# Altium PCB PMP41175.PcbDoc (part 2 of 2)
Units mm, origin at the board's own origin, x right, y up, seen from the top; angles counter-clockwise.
Board outline 50 x 29 mm, 6 copper layers (Top Layer, Signal Layer 1, Signal Layer 2, Signal Layer 3, Signal Layer 4, Bottom Layer), stack 1.56 mm thick; 56 components, 26 nets, 110 pads, 28 vias.
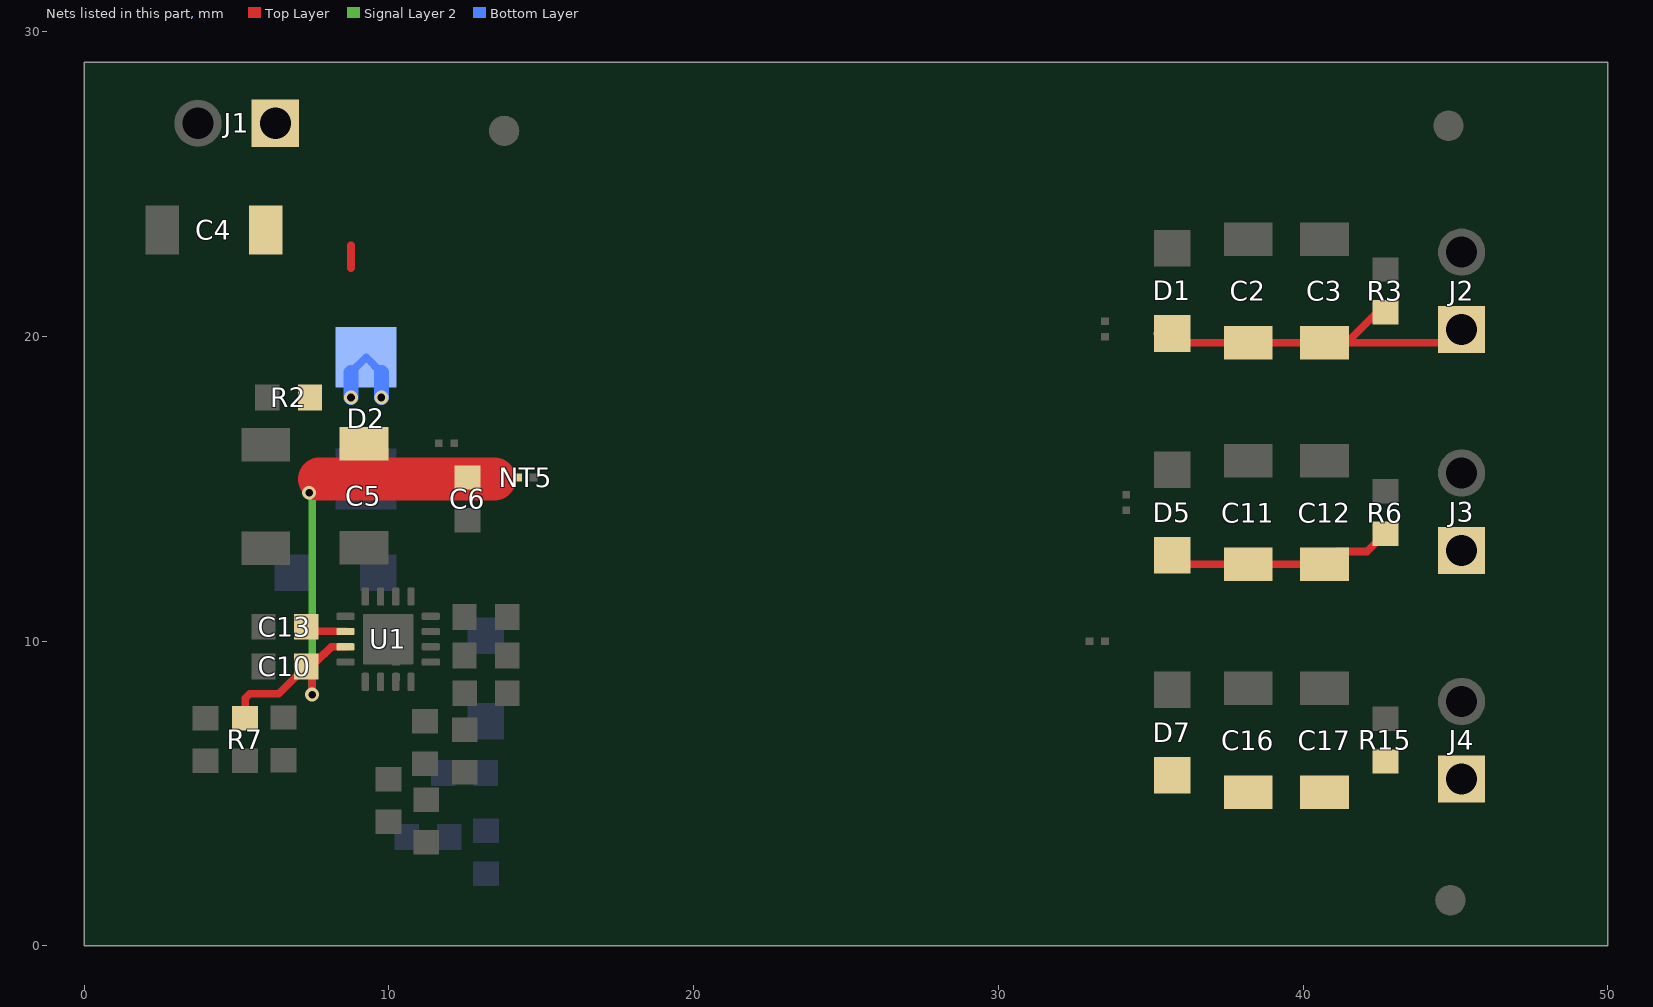
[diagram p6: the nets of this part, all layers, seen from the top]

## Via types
v1: diameter 0.457, hole 0.254, Top Layer to Bottom Layer, 15 vias
v2: diameter 0.4, hole 0.2, Top Layer to Bottom Layer, 8 vias
v3: diameter 0.5, hole 0.2, Top Layer to Bottom Layer, 5 vias

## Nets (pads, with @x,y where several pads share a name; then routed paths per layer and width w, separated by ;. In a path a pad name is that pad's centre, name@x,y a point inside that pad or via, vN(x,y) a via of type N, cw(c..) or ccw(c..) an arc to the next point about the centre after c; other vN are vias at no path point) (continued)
VBIAS: C4.1 C5.1 C6.1 C10.1 D2.2 J1.1 NT5.2 R2.2 R7.1 U1.3 | length 23.3
  Top Layer w0.254: R7.1@5.304,7.473 R7.1@5.279,7.473 5.279,8.124 5.428,8.273 6.379,8.273 C10.1@7.279,9.173 7.479,8.973 v1(7.479,8.244) ; C10.1@7.479,9.173 7.479,9.198 7.879,9.598 7.896,9.598 8.114,9.816 U1.3@8.572,9.816 ; 8.75,22.25 8.75,23 ; C6.1@12.579,15.373 NT5.2@14.175,15.373
  Top Layer w1.4: 7.706,15.323 13.462,15.323
  Signal Layer 2 w0.254: v1(7.379,14.873) 7.379,14.818 7.479,14.718 v1(7.479,8.244)
  Bottom Layer w0.254: D2.2@8.75,18.82 D2.2@9.25,19.32 D2.2@9.75,18.82
  Bottom Layer w0.5: v1(8.75,18) D2.2@8.75,18.82 ; v1(9.75,18) D2.2@9.75,18.82
VCC: C13.1 U1.2 | length 1.1
  Top Layer w0.254: C13.1@7.479,10.373 C13.1@7.529,10.423 ; C13.1@7.529,10.323 U1.2@8.579,10.323
VOUT1: C2.1 C3.1 D1.1 J2.1 R3.2 | length 12.3
  Top Layer w0.254: D1.1@35.206,20.1 35.506,19.8 C3.1@41.431,19.8 ; R3.2@42.456,20.8 42.431,20.8 C3.1@41.431,19.8 ; J2.1@45.206,20.23 44.776,19.8 C3.1@41.431,19.8
  Bottom Layer w0.254: J2.1@44.839,19.863 J2.1@45.206,20.23
VOUT2: C11.1 C12.1 D5.1 J3.1 R6.2 | length 8.1
  Top Layer w0.254: D5.1@35.706,12.824 36.006,12.524 C11.1@38.206,12.524 C12.1@40.706,12.524 41.129,12.947 42.104,12.947 42.681,13.524 R6.2@42.706,13.524
  Bottom Layer w0.254: J3.1@44.839,12.612 J3.1@45.206,12.98
VOUT3: C16.1 C17.1 D7.1 J4.1 R15.2 | length 0.5
  Bottom Layer w0.254: J4.1@44.839,5.112 J4.1@45.206,5.48
pads on no net: FID1.1 FID2.1 FID3.1 U1.4 U1.12 U1.15

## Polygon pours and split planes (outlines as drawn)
VBIAS on Top Layer "TOP_LAYER_VBIAS_P042" (solid, pour order 42): 10.5,22.5 10.5,15.291 6.956,15.291 6.956,19.544 6.956,22.5
GND3 on Top Layer "TOP_LAYER_GND3_P060" (solid, pour order 60): 47.956,7.5 47.206,6.75 34.206,6.75 33.456,7.5 33.456,10.156 33.8,10.5 47.206,10.5 47.956,9.75
GND2 on Top Layer "TOP_LAYER_GND2_P055" (solid, pour order 55): 47.956,15 47.206,14.25 34.206,14.25 33.456,15 33.456,17 34.207,17.751 47.205,17.751 47.956,17
GND1 on Top Layer "TOP_LAYER_GND1_P053" (solid, pour order 53): 47.956,22.25 47.206,21.5 33.956,21.5 33.206,22.25 33.206,24.25 33.956,25 47.206,25 47.956,24.25
PGND on Top Layer "TOP_LAYER_PGND_P044" (solid, pour order 44): 14.706,22.498 10.75,22.498 10.75,16.886 10.886,16.75 12.25,16.75 14.706,19.206
PGND on Top Layer "TOP_LAYER_PGND_P043" (solid, pour order 43): 0.5,28.284 3.216,28.284 4.25,27.25 4.25,20.75 4.586,20.414 6.196,20.414 13.206,13.405 13.206,5.957 14.648,5.957 14.826,5.779 14.826,3.442 14.956,3.312 14.956,0.496 0.5,0.496
SW on Top Layer "TOP_LAYER_SW_P040" (solid, pour order 40): 10.081,11.975 11.288,13.182 12.181,13.182 12.158,12.352 10.979,11.173 10.081,11.173
VBIAS on Top Layer "TOP_LAYER_VBIAS_P041" (solid, pour order 41): 10.5,22.75 10.75,23 10.75,25.5 7.865,28.385 5.5,28.385 5.5,22.75
AGND on Top Layer "TOP_LAYER_AGND_P039" (solid, remove dead copper, pour order 39): 14.956,2.884 14.956,11.273 13.379,11.273 13.379,4.173 11.484,4.173 10.484,5.173 10.539,5.228 10.539,8.673 9.764,8.673 9.456,8.365 9.456,7.645 6.959,5.148 5.784,5.148 5.784,3.973 6.873,2.884
GND1 on Bottom Layer "BOTTOM_LAYER_GND1_P059" (solid, pour order 59): 33.956,18.75 33.206,19.5 33.206,24.25 33.956,25 47.206,25 47.956,24.25 47.956,19.5 47.206,18.75
GND3 on Bottom Layer "BOTTOM_LAYER_GND3_P057" (solid, pour order 57): 34.206,4 33.456,4.75 33.456,9.75 34.206,10.5 47.206,10.5 47.956,9.75 47.956,4.75 47.206,4
GND2 on Bottom Layer "BOTTOM_LAYER_GND2_P054" (solid, pour order 54): 34.206,11.5 33.456,12.25 33.456,17 34.206,17.75 47.206,17.75 47.956,17 47.956,12.25 47.206,11.5
PGND on Bottom Layer "BOTTOM_LAYER_PGND_P052" (solid, pour order 52): 9.619,20.181 10.206,20.768 10.206,22.51 14.713,22.51 14.713,18.507 14.713,11.345 14.953,11.106 14.953,3.417 14.953,0.496 -2.04,0.496 -2.294,0.75 -2.294,19.292 -1.405,20.181
GND1 on Signal Layer 1 "SIGNAL_LAYER_1_GND1_P058" (solid, pour order 58): 33.956,18.75 33.206,19.5 33.206,24.25 33.956,25 47.206,25 47.956,24.25 47.956,19.5 47.206,18.75
GND3 on Signal Layer 1 "SIGNAL_LAYER_1_GND3_P056" (solid, pour order 56): 34.206,4 33.456,4.75 33.456,9.75 34.206,10.5 47.206,10.5 47.956,9.75 47.956,4.75 47.206,4
GND2 on Signal Layer 1 "SIGNAL_LAYER_1_GND2_P049" (solid, pour order 49): 34.206,11.5 33.456,12.25 33.456,17 34.206,17.75 47.206,17.75 47.956,17 47.956,12.25 47.206,11.5
PGND on Signal Layer 1 "SIGNAL_LAYER_1_PGND_P045" (solid, pour order 45): 10.206,22.5 14.706,22.5 14.706,18.5 14.25,18.044 14.25,11.816 14.953,11.113 14.953,3.417 14.953,0.496 -2.04,0.496 -2.294,0.75 -2.294,19.292 -1.405,20.181 9.637,20.181 10.206,20.75
PGND on Signal Layer 2 "SIGNAL_LAYER_2_PGND_P046" (solid, pour order 46): 9.637,20.181 10.206,20.75 10.206,22.5 14.706,22.5 14.706,18.5 13.479,17.273 13.479,12.444 14.956,10.968 14.956,0.496 -2.04,0.496 -2.294,0.75 -2.294,19.292 -1.405,20.181
PGND on Signal Layer 3 "SIGNAL_LAYER_3_PGND_P050" (solid, pour order 50): 9.637,20.181 10.206,20.75 10.206,22.5 14.706,22.5 14.706,18.5 13.479,17.273 13.479,9.005 14.953,7.532 14.953,3.417 14.953,0.496 -2.04,0.496 -2.294,0.75 -2.294,19.292 -1.405,20.181
PGND on Signal Layer 4 "SIGNAL_LAYER_4_PGND_P048" (solid, pour order 48): 9.619,20.181 10.206,20.768 10.206,22.506 14.706,22.506 14.706,18.5 13.479,17.273 13.479,9.005 14.953,7.532 14.953,3.417 14.953,0.496 -2.04,0.496 -2.294,0.75 -2.294,19.292 -1.405,20.181
no net on Signal Layer 4 "SIGNAL_LAYER_4_NONET_P047" (solid, pour order 47): 10.124,12.218 11.179,13.273 11.999,13.273 11.999,12.353 10.868,11.373 10.868,11.188 10.124,11.188

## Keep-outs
Keep-Out Layer:
  text ".Layer_Name" at 14.656,-21.806 h1.52

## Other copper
Top Layer:
  rectangle net VOUT1: 34.706,18.75 46.456,21.125
  rectangle net VOUT3: 34.706,4 46.456,6.5
  rectangle net VOUT2: 34.706,11.5 46.456,13.875
  text ".Layer_Name" at 14.656,-21.806 h1.52
Bottom Layer:
  text ".Layer_Name" at 14.656,-21.806 h1.52

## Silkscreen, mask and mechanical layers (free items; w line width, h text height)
Top Overlay:
  circle w0.1: c22.86,14.351 r4.4
  lines w0.1: 16.155,8.348 ccw(c22.86,14.351) 29.564,8.347 ; 18.949,12.362 16.151,8.342 15.86,8.051 15.86,4.101 29.86,4.101 29.86,8.051 29.569,8.342 26.771,12.334 26.76,12.351 ; 18.949,16.368 16.156,20.355 cw(c22.86,14.351) 29.565,20.354 ; 26.771,16.368 29.569,20.36 29.86,20.651 29.86,24.601 15.86,24.601 15.86,20.651 16.16,20.351 ; 16.16,20.351 16.16,20.351
  text "VIN" at 9.322,25.678 h1.02 r90
  text "GND" at 1.822,25.428 h1.02 r90
  text "-" at 46.884,22.17 h1.02
  text "+" at 46.884,19.759 h1.02
  text "Vout1" at 44.583,17.877 h0.76
  text "-" at 46.884,14.92 h1.02
  text "+" at 46.884,12.509 h1.02
  text "Vout2" at 44.083,10.627 h0.76
  text "-" at 46.884,7.42 h1.02
  text "+" at 46.884,5.009 h1.02
  text "Vout3" at 44.083,3.127 h0.76
  text "PMP41175-E1" at 31.75,1 h2.03
  text "'.PRJ_Number'.PCB_Rev" at 31.5,-4.5 h2.03
  text ".Layer_Name" at 14.656,-21.806 h1.52
Bottom Overlay:
  circle w0.1: c22.86,14.351 r4.4
  lines w0.1: 16.155,8.348 ccw(c22.86,14.351) 29.564,8.347 ; 18.949,12.362 16.151,8.342 15.86,8.051 15.86,4.101 29.86,4.101 29.86,8.051 29.569,8.342 26.771,12.334 26.76,12.351 ; 18.949,16.368 16.156,20.355 cw(c22.86,14.351) 29.565,20.354 ; 26.771,16.368 29.569,20.36 29.86,20.651 29.86,24.601 15.86,24.601 15.86,20.651 16.16,20.351 ; 16.16,20.351 16.16,20.351
  text ".Layer_Name" at 14.656,-21.806 h1.52
Top Paste:
  text ".Layer_Name" at 14.656,-21.806 h1.52
Bottom Paste:
  text ".Layer_Name" at 14.656,-21.806 h1.52
Top Solder:
  rectangle: 8.25,22.75 9.25,23
  rectangle: 8.25,22.25 9.25,22.5
  rectangle: 7.25,23 10.25,23.75
  rectangle: 7.25,21.5 10.25,22.25
  text ".Layer_Name" at 14.656,-21.806 h1.52
  text ".Layer_Name" at 14.656,-21.806 h1.52
Bottom Solder:
  text ".Layer_Name" at 14.656,-21.806 h1.52
Drill Guide:
  text ".Layer_Name" at 14.656,-21.806 h1.52
M1 Board Outline:
  circle w0.1: c22.86,14.351 r4.55
  lines w0.1: 15.944,8.837 15.36,8.251 15.36,3.601 30.36,3.601 30.36,8.251 29.769,8.839 29.337,8.839 ; 15.951,8.839 16.383,8.839 ; 15.951,19.863 16.383,19.863 ; 15.951,19.865 15.36,20.451 15.36,25.101 30.36,25.101 30.36,20.451 29.784,19.865 ; 16.39,19.863 cw(c22.86,14.351) 29.331,19.862 ; 16.394,8.834 ccw(c22.86,14.351) 29.333,8.842 ; 29.337,19.863 29.769,19.863
  lines w0.254: 0,0 0,29 50,29 50,0 0,0
  text ".Layer_Name" at 14.656,-21.806 h1.52
M2 Board Dimensions:
  rectangle: 0,-6.985 3.175,-3.81
  rectangle: 3.175,-10.16 12.7,-6.985
  lines w0.178: 0,-6.985 25.4,-6.985 ; 3.175,-10.16 3.175,-3.81 ; 6.35,-10.16 6.35,-3.81 ; 12.7,-10.16 12.7,-3.81 ; 19.05,-10.16 19.05,-3.81 ; 0,-10.16 25.4,-10.16 25.4,-3.81 0,-3.81 0,-10.16
  text ".Layer_Name" at 14.656,-21.806 h1.52
M3 3D STEP Top:
  text ".Layer_Name" at 14.656,-21.806 h1.52
M4 3D STEP Bottom:
  text ".Layer_Name" at 14.656,-21.806 h1.52
M5 Assembly Top:
  lines w0.254: -7.417,-23.626 160.223,-23.626 ; -7.417,-18.462 160.274,-18.462 ; -7.417,-13.297 -7.417,-28.791 94.31,-28.791 160.274,-28.791 160.274,-13.297 -7.404,-13.297 -7.404,-28.791 32.614,-28.791 ; 55.194,-28.791 55.194,-13.297 ; 87.376,-18.462 87.376,-13.297 ; 108.712,-18.462 108.712,-13.297 ; 124.511,-28.956 124.511,-23.804
  text "COMPONENTS MARKED 'DNP' SHOULD NOT BE POPULATED." at 29.299,-8.09 h1.52
  text "ASSEMBLY VARIANT:" at 29.286,-11.024 h1.52
  text ".VariantName" at 55.601,-11.024 h1.52
  text "PCB VIEWED FROM TOP SIDE" at -5.804,-16.654 h1.52
  text "BOARD #:" at 57.099,-16.654 h1.52
  text ".PRJ_Number" at 70.955,-16.654 h1.52
  text "REV:" at 92.405,-16.654 h1.52
  text ".PCB_Rev" at 99.809,-16.654 h1.52
  text "SVN REV:" at 113.69,-16.654 h1.52
  text ".VersionControl_RevNumber" at 126.543,-16.654 h1.52
  text "TID #:" at 57.099,-21.819 h1.52
  text ".TID" at 70.955,-21.819 h1.52
  text "PLOT NAME =" at -5.804,-27.034 h1.52
  text ".plot_File_Name" at 14.656,-27.034 h1.52
  text "GENERATED    :" at 57.15,-27.034 h1.52
  text ".Print_Date" at 79.235,-27.034 h1.52
  text ".Print_Time" at 97.752,-27.034 h1.52
  text "TEXAS INSTRUMENTS" at 129.87,-27.034 h1.52
M6 Assembly Bottom:
  lines w0.254: -7.429,-18.474 160.261,-18.474 ; -7.379,-23.639 160.261,-23.639 ; 28.334,-28.969 28.334,-23.817 ; 44.133,-18.474 44.133,-13.31 ; 65.468,-18.474 65.468,-13.31 ; 97.65,-28.804 97.65,-13.31 ; 120.231,-28.804 160.249,-28.804 160.249,-13.31 -7.429,-13.31 -7.429,-28.804 58.534,-28.804 160.261,-28.804 160.261,-13.31
  text "COMPONENTS MARKED 'DNP' SHOULD NOT BE POPULATED." at 154.991,-8.077 h1.52
  text ".VariantName" at 128.473,-11.024 h1.52
  text "ASSEMBLY VARIANT:" at 154.864,-11.024 h1.52
  text ".VersionControl_RevNumber" at 26.302,-16.667 h1.52
  text "SVN REV:" at 39.154,-16.667 h1.52
  text ".PCB_Rev" at 53.035,-16.667 h1.52
  text "REV:" at 60.439,-16.667 h1.52
  text ".PRJ_Number" at 81.89,-16.667 h1.52
  text "BOARD #:" at 95.745,-16.667 h1.52
  text "PCB VIEWED FROM BOTTOM SIDE" at 158.648,-16.667 h1.52
  text ".TID" at 81.89,-21.831 h1.52
  text "TID #:" at 95.745,-21.831 h1.52
  text "TEXAS INSTRUMENTS" at 22.974,-27.047 h1.52
  text ".Print_Time" at 55.093,-27.047 h1.52
  text ".Print_Date" at 73.609,-27.047 h1.52
  text "GENERATED    :" at 95.694,-27.047 h1.52
  text ".plot_File_Name" at 138.189,-27.047 h1.52
  text "PLOT NAME =" at 158.648,-27.047 h1.52
M9 Title Sheet:
  drawing of 57 lines, arcs and shapes, not listed
  text "1" at 18.792,204.127 h1.78
  text "2" at 82.182,204.127 h1.78
  text "3" at 145.411,204.127 h1.78
  text "4" at 209.08,204.127 h1.78
  text "5" at 272.555,204.127 h1.78
  text "6" at 336.182,204.127 h1.78
  text "A" at -10.579,175.095 h1.78
  text "A" at 365.341,175.095 h1.78
  text "B" at -10.579,114.643 h1.78
  text "B" at 365.341,114.643 h1.78
  text "C" at -10.579,54.318 h1.78
  text "C" at 365.341,54.318 h1.78
  text "PROJECT TITLE:" at 288.125,7.048 h1.14
  text ".PRJ_Title" at 289.395,3.662 h1.78
  text "DESIGNED FOR:" at 288.125,-0.597 h1.14
  text ".PRJ_Customer" at 289.395,-4.153 h1.78
  text "D" at -10.579,-5.88 h1.78
  text "D" at 365.341,-5.88 h1.78
  text "FILE NAME:" at 288.125,-8.217 h1.14
  text ".PCB_File_Name_No_Path" at 289.395,-11.265 h1.78
  text "Texas Instruments (TI) and/or its licensors do not warrant the accuracy or completeness of this specification" at 161.9,-15.376 h1.14
  text "ENGINEER:" at 288.125,-15.583 h1.14
  text "LAYOUT BY:" at 326.352,-15.583 h1.14
  text "or any information contained therein. TI and/or its licensors do not warrant that this design will meet" at 160.757,-18.237 h1.14
  text ".PRJ_Engineer" at 289.395,-19.52 h1.78
  text ".PCB_Layout" at 327.635,-19.52 h1.78
  text "the specifications, will be suitable for your application or fit for any particular purpose, or will operate in" at 160.757,-21.099 h1.14
  text ".Layer_Name" at 14.656,-21.806 h1.52
  text "ALTIUM DESIGNER VERSION:" at 326.352,-23.457 h1.14
  text "an implementation. TI and/or its licensors do not warrant that the design is production worthy. You should" at 160.757,-23.961 h1.14
  text "completely validate and test your design implementation to confirm the system functionality for your application." at 161.9,-26.822 h1.14
  text ".print_Scale" at 289.395,-26.843 h1.78
  text ".Application_BuildNumber" at 327.635,-26.843 h1.78
  text "1" at 18.792,-32.093 h1.78
  text "2" at 82.182,-32.093 h1.78
  text "3" at 145.411,-32.093 h1.78
  text "4" at 209.08,-32.093 h1.78
  text "5" at 272.555,-32.093 h1.78
  text "6" at 336.182,-32.093 h1.78
M10 Fab Notes:
  drawing of 189 lines, arcs and shapes, not listed
  text "DESIGN INFORMATION" at 314.503,161.447 h1.52
  text "MIN. TRACK WIDTH:" at 298.131,158.091 h1.52
  text "8" at 325.976,158.091 h1.52
  text "MIL" at 329.907,158.091 h1.52
  text "7.874" at 321.75,155 h1.52
  text "MIN. CLEARANCE:" at 298.131,154.938 h1.52
  text "MIL" at 329.907,154.938 h1.52
  text "MIN. VIA PAD SIZE:" at 298.131,151.785 h1.52
  text "24" at 325.214,151.785 h1.52
  text "MIL" at 329.907,151.785 h1.52
  text "0.05mm (2MIL)" at 315.784,148.486 h1.52
  text "MINIMUM ANNULAR RING" at 289.769,148.277 h1.52
  text "EXTERNAL" at 333.768,148.277 h1.52
  text "PER" at 294.849,145.48 h1.52
  text "IPC-D-275 CLASS 2 LEVEL C" at 300.437,145.48 h1.52
  text "MIL, HOLES" at 338.238,142.928 h1.52
  text "+/-" at 328.27,142.709 h1.52
  text "+/-" at 349.961,142.709 h1.52
  text "REGISTRATION TOLERANCES:" at 289.769,142.682 h1.52
  text "METAL" at 320.243,142.682 h1.52
  text "5" at 334.879,142.683 h1.52
  text "3" at 356.037,142.683 h1.52
  text "MIL" at 358.99,142.682 h1.52
  text "HOLE SIZE TOLERANCE (UNLESS OTHERWISE SPECIFIED):" at 289.769,140.185 h1.52
  text "+/-" at 349.961,140.112 h1.52
  text "3" at 356.037,140.085 h1.52
  text "MIL" at 358.99,140.085 h1.52
  text "MATERIAL:" at 287.87,136.589 h1.52
  text "FR-4 High Tg" at 312.926,133.324 h1.52
  text "X" at 309.257,133.122 h1.52
  text "FR-4" at 298.563,133.007 h1.52
  text "OTHER" at 336.358,133.007 h1.52
  text "62 MIL (1.6mm) +/-10%" at 306.694,129.374 h1.52
  text "X" at 303.643,129.312 h1.52
  text "THICKNESS:" at 289.769,129.165 h1.52
  text "OTHER" at 339.33,129.165 h1.52
  text "TOLERANCE:" at 289.769,125.652 h1.52
  text "X" at 311.314,125.652 h1.52
  text "ANSI IPC-6012 TYPE 3 CLASS 2" at 315.836,125.652 h1.52
  text "OTHER +/-" at 315.835,121.989 h1.52
  text "BOW & TWIST:" at 289.769,118.302 h1.52
  text "X" at 311.314,118.302 h1.52
  text "ANSI IPC-6012 TYPE 3 CLASS 2" at 315.836,118.302 h1.52
  text "OTHER +/-" at 315.835,114.576 h1.52
  text "DRILLING:" at 287.87,111.258 h1.52
  text "NC_DRILL FILES" at 332.599,108.586 h1.52
  text "REFERENCE:" at 289.769,108.486 h1.52
  text "X" at 306.463,108.484 h1.52
  text "AS SHOWN" at 310.984,108.486 h1.52
  text "X" at 329.348,108.486 h1.52
  text "OTHER" at 340.168,104.873 h1.52
  text "PTH COPPER THICKNESS:" at 289.761,104.783 h1.52
  text "X" at 318.697,104.783 h1.52
  text "20-30 um" at 321.948,104.783 h1.52
  text "BOARD FINISH:" at 287.87,101.034 h1.52
  text "SILKSCREEN:" at 291.812,98.237 h1.52
  text "X" at 316.14,98.237 h1.52
  text "TOP" at 319.112,98.237 h1.52
  text "X" at 329.094,98.237 h1.52
  text "BOTTOM" at 332.091,98.237 h1.52
  text "SILKSCREEN COLOR:" at 291.812,94.295 h1.52
  text "X" at 316.115,94.295 h1.52
  text "WHITE" at 319.112,94.295 h1.52
  text "OTHER" at 332.091,94.295 h1.52
  text "X" at 319.442,90.652 h1.52
  text "GREEN" at 322.439,90.652 h1.52
  text "OTHER" at 338.136,90.652 h1.52
  text "SOLDER RESIST COLOR:" at 291.812,90.477 h1.52
  text "X" at 319.442,86.734 h1.52
  text "MATTE" at 322.439,86.734 h1.52
  text "SEMI-GLOSS" at 338.125,86.717 h1.52
  text "IMMERSION GOLD (ENIG)" at 314.819,82.345 h1.52
  text "ENEPIG" at 348.793,82.162 h1.52
  text "SURFACE FINISH:" at 287.87,82.136 h1.52
  text "X" at 310.298,82.136 h1.52
  text "IMM. TIN/SILVER OR EQUIV" at 296.24,78.649 h1.52
  text "OTHER" at 332.599,78.549 h1.52
  text "ARRAY/PANEL:" at 287.87,74.602 h1.52
  text "CUT AND TRIM PER M1 BOARD OUTLINE" at 314.819,74.393 h1.52
  text "N.C. ROUTE" at 314.819,70.94 h1.52
  text "X" at 332.295,70.94 h1.52
  text "V. SCORE" at 336.816,70.94 h1.52
  text "CERTIFICATION:" at 287.87,67.66 h1.52
  text "MATERIALS AND WORKMANSHIP FOR ALL PCBS" at 306.285,67.66 h1.52
  text "TO MEET OR EXCEED THE REQUIREMENTS OF:" at 306.285,65.271 h1.52
  text "X" at 297.078,62.003 h1.52
  text "ANSI IPC-A-600F CLASS ->" at 300.329,62.003 h1.52
  text "X" at 342.188,62.003 h1.52
  text "2" at 344.982,62.003 h1.52
  text "1" at 336.981,61.965 h1.52
  text "3" at 353.973,61.965 h1.52
  text "X" at 317.702,58.252 h1.52
  text "RoHS" at 320.953,58.252 h1.52
  text "OTHER" at 337.321,58.252 h1.52
  text "PER ORDER" at 347.407,58.252 h1.52
  text "ALL BOARDS MUST MEET OR EXCEED UL94-V0 REQUIREMENTS." at 288.569,54.345 h1.52
  text "PCB MUST BEAR THE UL94V-0 UL REGISTERED MATERIAL ID NUMBER" at 288.569,51.397 h1.52
  text "ADDITIONAL REQUIREMENTS:" at 287.87,47.094 h1.52
  text "MICROSECTION:" at 289.769,44.373 h1.52
  text "YES" at 312.775,44.373 h1.52
  text "REQUIRED" at 334.657,40.707 h1.52
  text "BARE BOARD ELEC. TEST:" at 289.769,40.634 h1.52
  text "NONE" at 322.935,40.634 h1.52
  text "X" at 331.66,40.634 h1.52
  text "PER ORDER" at 349.693,40.634 h1.52
  text "XX MIL VIAS REQUIRE NON-CONDUCTIVE FILL AND PLANARIZE" at 294.04,35.428 h1.5
  text "XX MIL VIAS REQUIRE CONDUCTIVE FILL AND PLANARIZE" at 294.243,32.787 h1.52
  text "OUTER XX MIL TRACES REQUIRE 50 OHM SINGLE-ENDED IMPEDANCE" at 294.218,28.637 h1.47
  text "LAYER 2 & 3 (INNER LAYERS) XX MIL WIDE, XX MIL SPACE / TRACES REQUIRE 100 OHM DIFFERENTIAL IMPEDANCE" at 294.015,22.65 h1.52
  text ".Layer_Name" at 14.656,-21.806 h1.52
M11 Gerber Information:
  lines w0.254: -7.417,-23.626 160.223,-23.626 ; -7.417,-18.462 160.274,-18.462 ; -7.417,-13.297 -7.417,-28.791 94.31,-28.791 160.274,-28.791 160.274,-13.297 -7.404,-13.297 -7.404,-28.791 32.614,-28.791 ; 55.194,-28.791 55.194,-13.297 ; 87.376,-18.462 87.376,-13.297 ; 108.712,-18.462 108.712,-13.297 ; 124.511,-28.956 124.511,-23.804
  text "ALL ARTWORK VIEWED FROM TOP SIDE" at -5.804,-16.654 h1.52
  text "BOARD #:" at 57.099,-16.654 h1.52
  text ".PRJ_Number" at 70.955,-16.654 h1.52
  text "REV:" at 92.405,-16.654 h1.52
  text ".PCB_Rev" at 99.809,-16.654 h1.52
  text "SVN REV:" at 113.69,-16.654 h1.52
  text ".VersionControl_RevNumber" at 126.543,-16.654 h1.52
  text "LAYER NAME =" at -5.804,-21.806 h1.52
  text "TID #:" at 57.099,-21.819 h1.52
  text ".TID" at 70.955,-21.819 h1.52
  text "PLOT NAME =" at -5.804,-27.034 h1.52
  text ".plot_File_Name" at 14.656,-27.034 h1.52
  text "GENERATED    :" at 57.15,-27.034 h1.52
  text ".Print_Date" at 79.235,-27.034 h1.52
  text ".Print_Time" at 97.752,-27.034 h1.52
  text "TEXAS INSTRUMENTS" at 129.87,-27.034 h1.52
M12 Stackup:
  drawing of 399 lines, arcs and shapes, not listed
  text "Layer" at 249.469,200.023 h1.52
  text "Name" at 259.88,200.023 h1.52
  text "Material" at 283.75,200.023 h1.52
  text "Thickness" at 305.588,200.023 h1.52
  text "Constant" at 322.094,200.023 h1.52
  text "Board Layer Stack" at 336.568,200.023 h1.52
  text "Top Overlay" at 259.88,196.975 h1.52
  text "Top Solder" at 259.88,193.927 h1.52
  text "Solder Resist" at 283.75,193.927 h1.52
  text "0.50mil" at 305.588,193.927 h1.52
  text "3.5" at 322.094,193.927 h1.52
  text "1" at 249.469,190.879 h1.52
  text "Top Layer" at 259.88,190.879 h1.52
  text "1.40mil" at 305.588,190.879 h1.52
  text "Dielectric 1" at 259.88,187.831 h1.52
  text "FR-4 High Tg" at 283.75,187.831 h1.52
  text "7.00mil" at 305.588,187.831 h1.52
  text "4.2" at 322.094,187.831 h1.52
  text "2" at 249.469,184.783 h1.52
  text "Signal Layer 1" at 259.88,184.783 h1.52
  text "1.40mil" at 305.588,184.783 h1.52
  text "Dielectric 2" at 259.88,181.735 h1.52
  text "FR-4 High Tg" at 283.75,181.735 h1.52
  text "14.00mil" at 305.588,181.735 h1.52
  text "4.2" at 322.094,181.735 h1.52
  text "3" at 249.469,178.687 h1.52
  text "Signal Layer 2" at 259.88,178.687 h1.52
  text "1.40mil" at 305.588,178.687 h1.52
  text "Dielectric 4" at 259.88,175.639 h1.52
  text "FR-4 High Tg" at 283.75,175.639 h1.52
  text "11.00mil" at 305.588,175.639 h1.52
  text "4.2" at 322.094,175.639 h1.52
  text "4" at 249.469,172.591 h1.52
  text "Signal Layer 3" at 259.88,172.591 h1.52
  text "1.40mil" at 305.588,172.591 h1.52
  text "Dielectric 5" at 259.88,169.543 h1.52
  text "FR-4 High Tg" at 283.75,169.543 h1.52
  text "14.00mil" at 305.588,169.543 h1.52
  text "4.2" at 322.094,169.543 h1.52
  text "5" at 249.469,166.495 h1.52
  text "Signal Layer 4" at 259.88,166.495 h1.52
  text "1.40mil" at 305.588,166.495 h1.52
  text "Dielectric 3" at 259.88,163.447 h1.52
  text "FR-4 High Tg" at 283.75,163.447 h1.52
  text "7.00mil" at 305.588,163.447 h1.52
  text "4.2" at 322.094,163.447 h1.52
  text "6" at 249.469,160.399 h1.52
  text "Bottom Layer" at 259.88,160.399 h1.52
  text "1.40mil" at 305.588,160.399 h1.52
  text "Bottom Solder" at 259.88,157.351 h1.52
  text "Solder Resist" at 283.75,157.351 h1.52
  text "0.50mil" at 305.588,157.351 h1.52
  text "3.5" at 322.094,157.351 h1.52
  text "Bottom Overlay" at 259.88,154.303 h1.52
  text ".Layer_Name" at 14.656,-21.806 h1.52
M13 Component Bodies Top:
  text ".Layer_Name" at 14.656,-21.806 h1.52
M14 Component Bodies Bottom:
  text ".Layer_Name" at 14.656,-21.806 h1.52
M15 Courtyards Top:
  text ".Layer_Name" at 14.656,-21.806 h1.52
M16 Courtyards Bottom:
  text ".Layer_Name" at 14.656,-21.806 h1.52
Drill Drawing:
  lines w0.254: 85.192,30.039 86.598,30.039 86.598,31.445 85.192,31.445 85.192,30.039 ; 85.192,33.553 85.544,33.553 85.895,33.201 86.247,33.553 86.598,33.553 86.247,33.904 86.598,34.255 86.247,34.255 85.895,34.607 85.544,34.255 85.192,34.255 85.544,33.904 85.192,33.553 ; 85.192,37.769 86.598,37.769 85.895,36.364 85.192,37.769
  lines w0.305: 83.918,29.09 166.016,29.09 ; 83.918,38.577 166.016,38.577 ; 92.504,25.928 92.504,41.74 ; 100.941,25.928 100.941,41.74 ; 117.107,25.928 117.107,41.74 ; 123.691,25.928 123.691,41.74 ; 133.222,25.928 133.222,41.74 ; 151.626,25.928 151.626,41.74 ; 83.918,25.928 166.016,25.928 166.016,41.74 83.918,41.74 83.918,25.928
  text "Symbol" at 85.816,39.526 h1.83
  text "Quantity" at 93.453,39.526 h1.83
  text "Finished Hole Size" at 101.889,39.526 h1.83
  text "Plated" at 118.056,39.526 h1.83
  text "Hole Type" at 124.64,39.526 h1.83
  text "Drill Layer Pair" at 134.171,39.526 h1.83
  text "Hole Tolerance" at 152.574,39.526 h1.83
  text "13" at 93.453,36.364 h1.52
  text "7.87mil (0.200mm)" at 101.889,36.364 h1.52
  text "PTH" at 118.056,36.364 h1.52
  text "Round" at 124.64,36.364 h1.52
  text "Top Layer - Bottom Layer" at 134.171,36.364 h1.52
  text "15" at 93.453,33.201 h1.52
  text "10.00mil (0.254mm)" at 101.889,33.201 h1.52
  text "PTH" at 118.056,33.201 h1.52
  text "Round" at 124.64,33.201 h1.52
  text "Top Layer - Bottom Layer" at 134.171,33.201 h1.52
  text "8" at 93.453,30.039 h1.52
  text "40.16mil (1.020mm)" at 101.889,30.039 h1.52
  text "PTH" at 118.056,30.039 h1.52
  text "Round" at 124.64,30.039 h1.52
  text "Top Layer - Bottom Layer" at 134.171,30.039 h1.52
  text "36 Total" at 93.453,26.877 h1.52
  text ".Layer_Name" at 14.656,-21.806 h1.52
M17 Embedded Cavity:
  text ".Layer_Name" at 14.656,-21.806 h1.52
M18 Embedded Assembly:
  text ".Layer_Name" at 14.656,-21.806 h1.52
M19 Embedded Keepout:
  text ".Layer_Name" at 14.656,-21.806 h1.52

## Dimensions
0,0 to 0,29 on M2 Board Dimensions
0,-10.16 to 25.4,-10.16 on M2 Board Dimensions
0,0 to 50,0 on M2 Board Dimensions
